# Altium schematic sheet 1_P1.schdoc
size 429 x 307 mm; Symbol: Drawing-Symbol_A4; Device: Drawing-Symbol_A4; @Project Name: PBT_PCB; @Page Count: 1; @Update Date: 2026-06-25; @Create Date: 2026-04-29; @Schematic Name: Schematic3; @Page No: 1; @Page Name: P1; Company: EasyEDA.com; Version: V1.0; Page Size: A4; @Create Time: 15:17:22; @Update Time: 19:14:14; Width: 1655; Height: 1170; Region Start: 1; X Region Count: 6; Y Region Count: 4; Blade Width: 10; Title Block Position: 3; @Board Name: NRF board
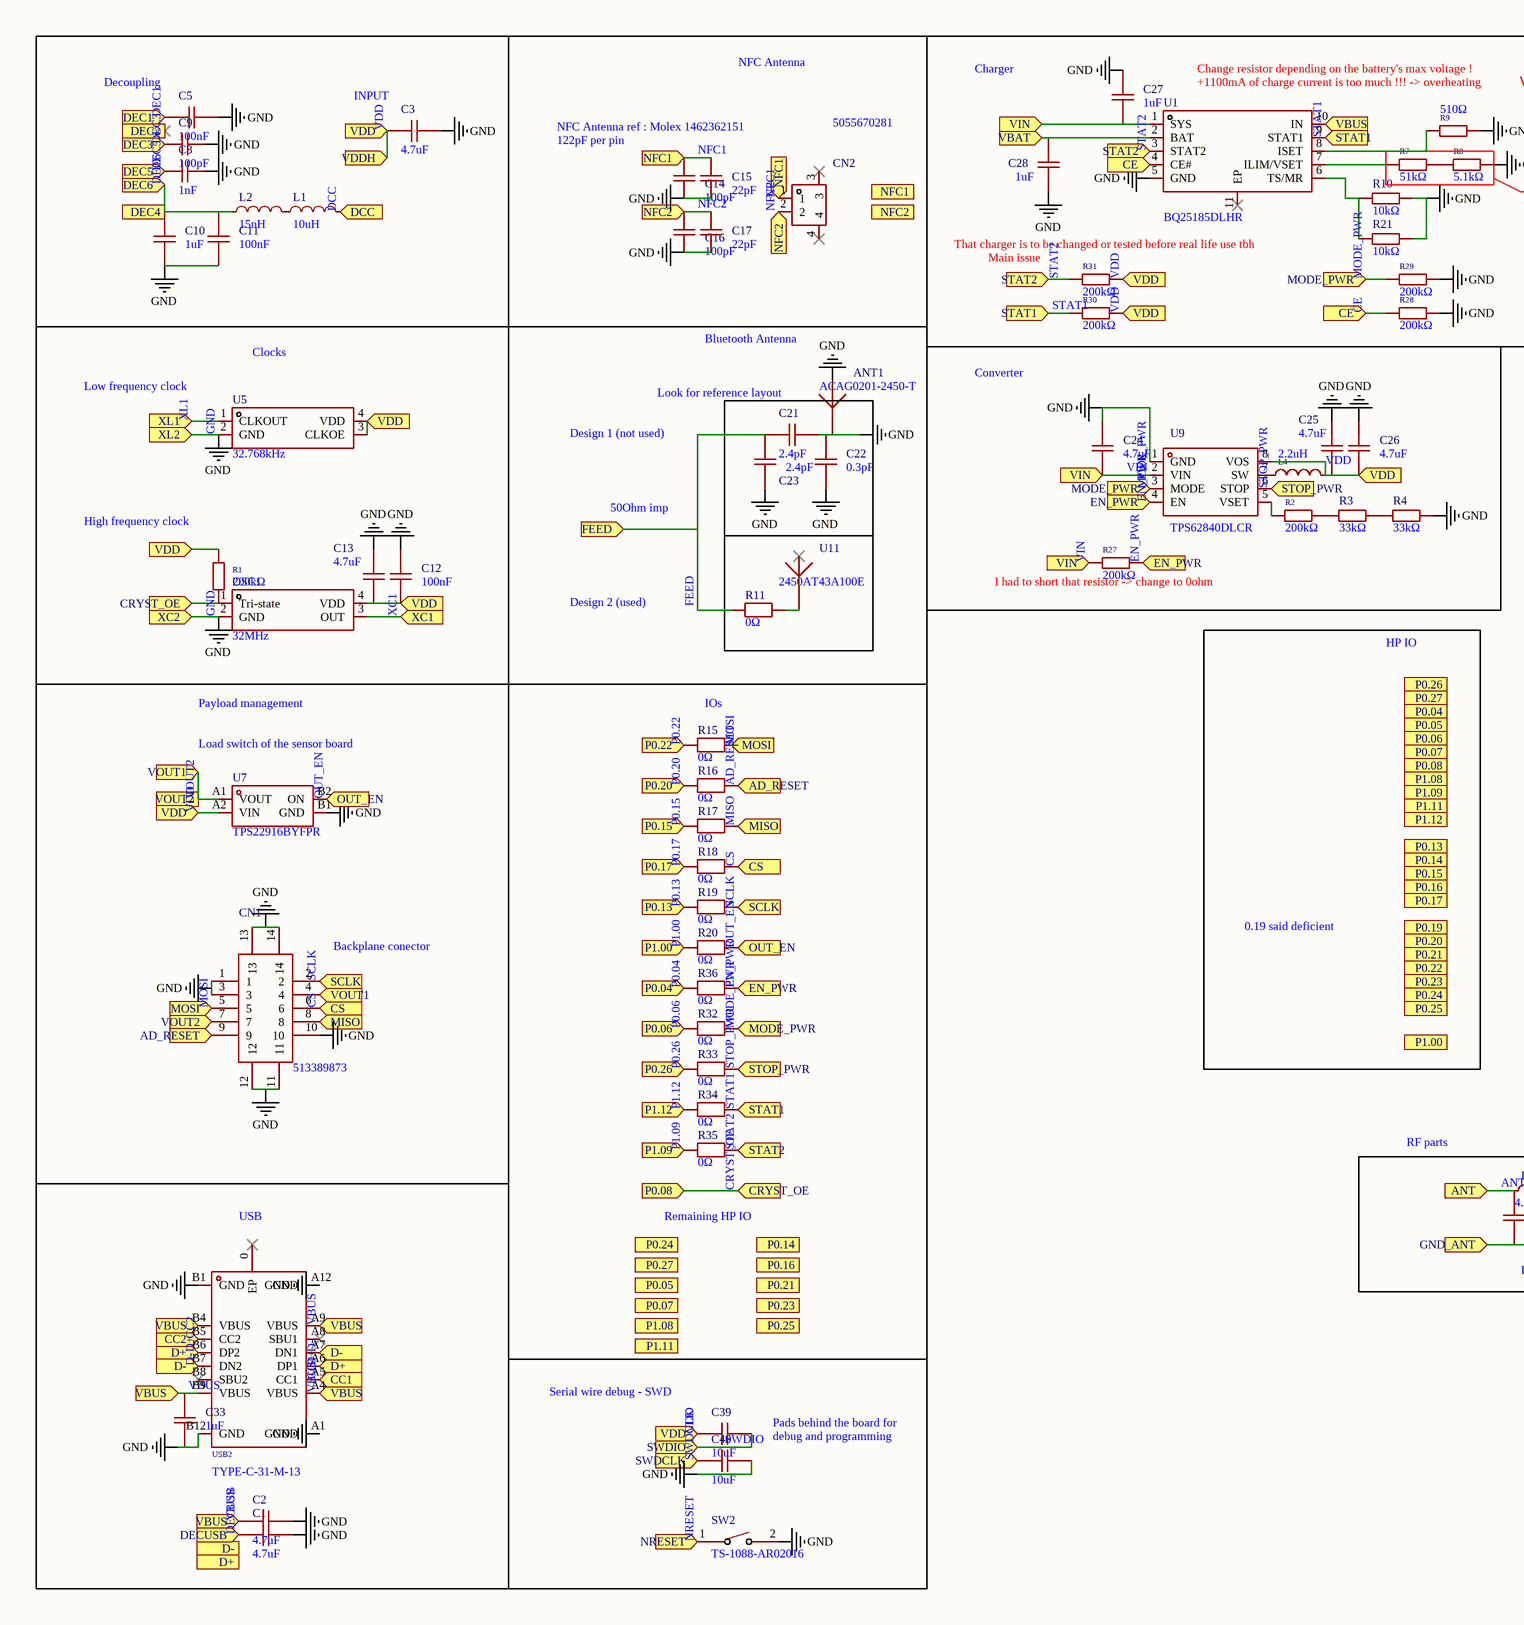
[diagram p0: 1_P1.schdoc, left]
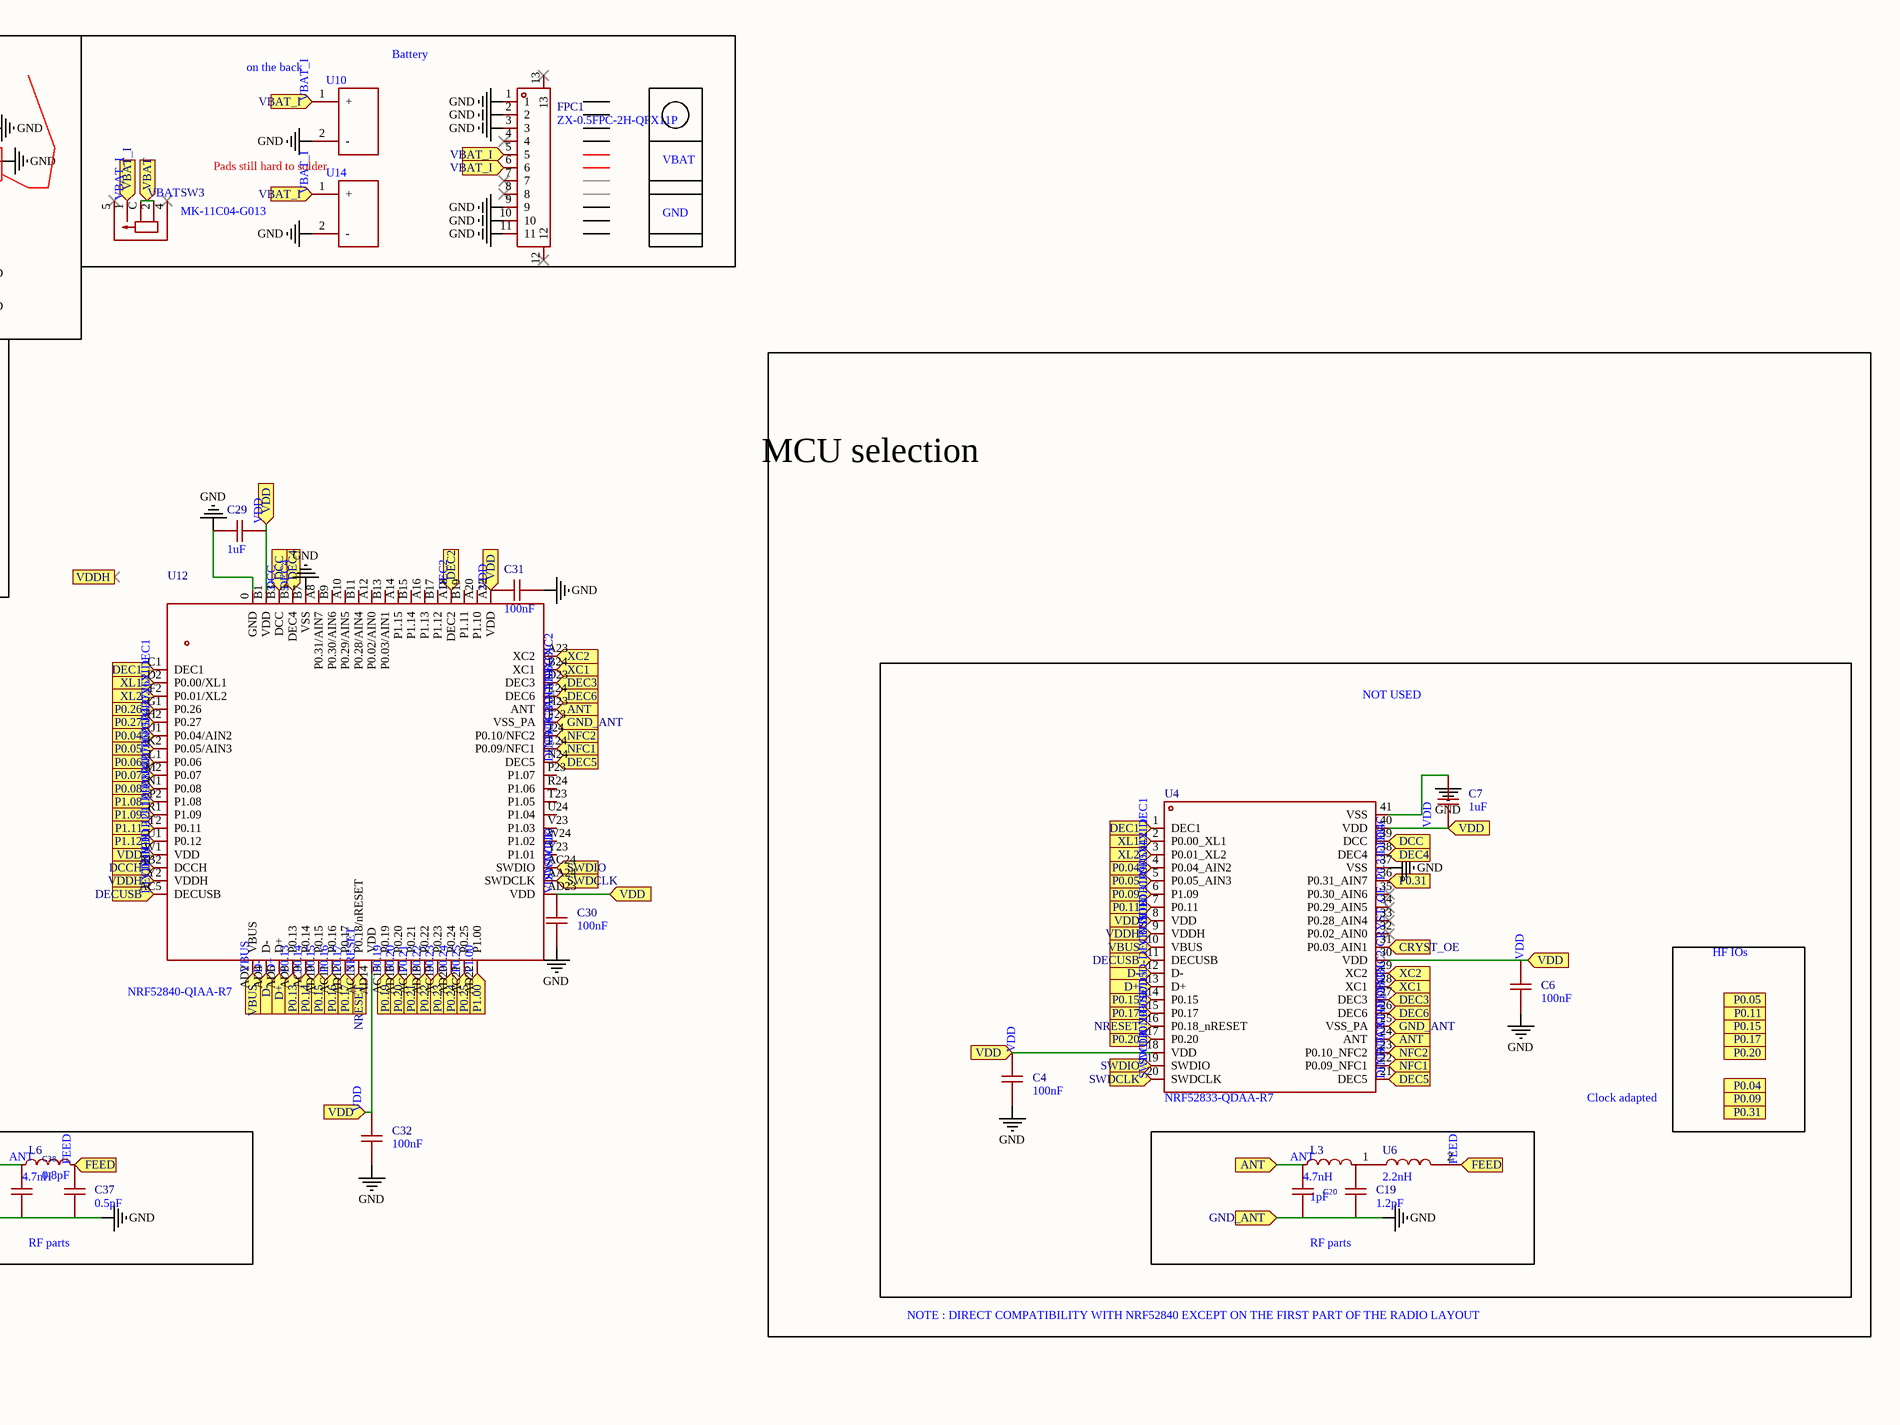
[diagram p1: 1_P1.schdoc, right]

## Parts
ANT1  ACAG0201-2450-T  [ANT-SMD_L2.0-W1.3_ACAG0201-2450-T]
C1  4.7uF  [C0402]
C2  4.7uF  [C0402]
C3  4.7uF  [C0402]
C4  100nF  [C0402]
C5  100nF  [C0402]
C6  100nF  [C0402]
C7  1uF  [C0402]
C8  1nF  [C0402]
C9  100pF  [C0402]
C10  1uF  [C0402]
C11  100nF  [C0402]
C12  100nF  [C0402]
C13  4.7uF  [C0402]
C14  100pF  [C0402]
C15  22pF  [C0402]
C16  100pF  [C0402]
C17  22pF  [C0402]
C19  1.2pF  [C0402]
C20  1pF  [C0402]
C21  2.4pF  [C0402]
C22  0.3pF  [C0603]
C23  2.4pF  [C0402]
C24  4.7uF  [C0402]
C25  4.7uF  [C0402]
C26  4.7uF  [C0402]
C27  1uF  [C0402]
C28  1uF  [C0402]
C29  1uF  [C0402]
C30  100nF  [C0402]
C31  100nF  [C0402]
C32  100nF  [C0402]
C33  1uF  [C0402]
C37  0.5pF  [C0402]
C38  0.8pF  [C0402]
C39  10uF  [C0805]
C40  10uF  [C0805]
CN1  513389873  [CONN-SMD_513389873]
CN2  5055670281  [CONN-SMD_2P-P1.25_MOLEX_5055670281]
FPC1  ZX-0.5FPC-2H-QFX11P  [FPC-SMD_11P-P0.50_ZX-0.5FPC-2H-QFX11P]
L1  10uH  [L0603]
L2  15nH  [IND-SMD_L1.2-W0.6]
L3  4.7nH  [L0402]
L4  2.2uH  [IND-SMD_L2.0-W1.6_MHCHL201610A-1R0M-Q8A]
L6  4.7nH  [L0402]
OSC1  32MHz  [OSC-SMD_4P-L3.2-W2.5-BL]
R1  200kΩ  [R0402]
R2  200kΩ  [R0402]
R3  33kΩ  [R0402]
R4  33kΩ  [R0402]
R7  51kΩ  [R0402]
R8  5.1kΩ  [R0402]
R9  510Ω  [R0402]
R10  10kΩ  [R0402]
R11  0Ω  [R0402]
R15  0Ω  [R0402]
R16  0Ω  [R0402]
R17  0Ω  [R0402]
R18  0Ω  [R0402]
R19  0Ω  [R0402]
R20  0Ω  [R0402]
R21  10kΩ  [R0402]
R27  200kΩ  [R0402]
R28  200kΩ  [R0402]
R29  200kΩ  [R0402]
R30  200kΩ  [R0402]
R31  200kΩ  [R0402]
R32  0Ω  [R0402]
R33  0Ω  [R0402]
R34  0Ω  [R0402]
R35  0Ω  [R0402]
R36  0Ω  [R0402]
SW2  TS-1088-AR02016  [SW-SMD_L3.9-W3.0-P4.45]
SW3  MK-11C04-G013  [SW-SMD_MK-11C04-G013]
U1  BQ25185DLHR  [WSON-10_L2.2-W2.0-P0.40-BL-EP_TI_DLH0010A]
U4  NRF52833-QDAA-R7  [QFN-40_L5.0-W5.0-P0.40-TL-EP3.6]
U5  32.768kHz  [OSC-SMD_4P-L3.2-W1.5-BL]
U6  2.2nH  [L0402]
U7  TPS22916BYFPR  [DSBGA-4_L0.8-W0.8-R2-C2-P0.40-BL]
U9  TPS62840DLCR  [VSON-8_L2.0-W1.5-P0.50-BL]
U10  (no value)  [CSSMR950SH_CONN]
U11  2450AT43A100E  [ANT-SMD_L7.0-W2.0-R]
U12  NRF52840-QIAA-R7  [AQFN-73_L7.0-W7.0-P0.50-BL-EP4.8]
U14  (no value)  [CSSMR950SH_CONN]
USB2  TYPE-C-31-M-13  [USB-C-SMD_TYPE-C-31-M-13]

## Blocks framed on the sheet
NFC Antenna: C14-C17 CN2
RF parts: C19 C20 L3 U6
USB: C1 C2 C33 USB2
Serial wire debug - SWD: C39 C40 SW2

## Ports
AD_RESET (in), ANT (in), CC1 (in), CC2 (in), CE (in), CRYST_OE (in), CS (in), D+ (in), D- (in), DCC (in), DCCH (in), DEC1 (in), DEC2 (in), DEC3 (in), DEC4 (in), DEC5 (in), DEC6 (in), DECUSB (in), EN_PWR (in), FEED (in), GND_ANT (in), MISO (in), MODE_PWR (in), MOSI (in), NFC1 (in), NFC2 (in), NRESET (in), OUT_EN (in), P0.04 (in), P0.05 (in), P0.06 (in), P0.07 (in), P0.08 (in), P0.09 (in), P0.11 (in), P0.13 (in), P0.14 (in), P0.15 (in), P0.16 (in), P0.17 (in), P0.19 (in), P0.20 (in), P0.21 (in), P0.22 (in), P0.23 (in), P0.24 (in), P0.25 (in), P0.26 (in), P0.27 (in), P0.31 (in), P1.00 (in), P1.08 (in), P1.09 (in), P1.11 (in), P1.12 (in), SCLK (in), STAT1 (in), STAT2 (in), STOP_PWR (in), SWDCLK (in), SWDIO (in), VBAT (in), VBAT_I (in), VBUS (in), VDD (in), VDDH (in), VIN (in), VOUT1 (in), VOUT2 (in), XC1 (in), XC2 (in), XL1 (in), XL2 (in)

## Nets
GND: ANT1.1 ANT1.2 C1.2 C2.2 C3.2 C4.2 C5.2 C6.2 C7.1 C8.2 C9.2 C10.1 C11.2 C12.1 C13.1 C14.2 C15.2 C16.2 C17.2 C19.2 C20.1 C21.2 C22.1 C22.2 C23.2 C24.1 C25.1 C26.1 C27.2 C28.2 C29.2 C30.2 C31.2 C32.2 C33.2 C37.2 C38.1 C40.1 CN1.1 CN1.3 CN1.10 CN1.11 CN1.12 CN1.13 CN1.14 FPC1.1 FPC1.2 FPC1.3 FPC1.9 FPC1.10 FPC1.11 OSC1.2(GND) R4.2 R8.2 R9.2 R10.2 R21.2 R28.2 R29.1 SW2.2 U1.5(GND) U4.3(P0.01_XL2) U4.25(VSS_PA) U4.29(XC2) U4.37(VSS) U4.41(VSS) U5.2(GND) U7.B1(GND) U9.1(GND) U10.2(-) U12.0(GND) U12.A23(XC2) U12.B7(VSS) U12.F2(P0.01/XL2) U12.F23(VSS_PA) U14.2(-) USB2.A1(GND) USB2.A12(GND) USB2.B1(GND) USB2.B12(GND) ; port XC2, port XL2, port GND_ANT  [also labelled GND_ANT, XC2, XL2]
AD_RESET: CN1.9 R16.2 ; port AD_RESET
ANT: C20.2 C38.2 L3.1 L6.1 U4.24(ANT) U12.H23(ANT) ; port ANT
CC1: USB2.A5(CC1) ; port CC1
CC2: USB2.B5(CC2) ; port CC2
CE: R28.1 U1.4(CE#) ; port CE
CRYST_OE: OSC1.1(Tri-state) R1.2 U4.31(P0.03_AIN1) U12.N1(P0.08) ; port CRYST_OE, port P0.08  [also labelled P0.08]
CS: CN1.6 R18.2 ; port CS
D+: U4.13(D+) U12.AD6(D+) USB2.A6(DP1) USB2.B6(DP2) ; port D+
D-: U4.12(D-) U12.AD4(D-) USB2.A7(DN1) USB2.B7(DN2) ; port D-
DCC: L1.2 U4.39(DCC) U12.B3(DCC) ; port DCC
DCCH: U12.AB2(DCCH) ; port DCCH
DEC1: C5.1 U4.1(DEC1) U12.C1(DEC1) ; port DEC1
DEC2: U12.A18(DEC2) ; port DEC2
DEC3: C9.1 U4.27(DEC3) U12.D23(DEC3) ; port DEC3
DEC4: C10.2 C11.1 L2.1 U4.26(DEC6) U4.38(DEC4) U12.B5(DEC4) U12.E24(DEC6) ; port DEC4, port DEC6  [also labelled DEC6]
DEC5: C8.1 U4.21(DEC5) U12.N24(DEC5) ; port DEC5
DECUSB: C1.1 U4.11(DECUSB) U12.AC5(DECUSB) ; port DECUSB
EN_PWR: R27.1 R36.2 U9.4(EN) ; port EN_PWR
FEED: C21.1 C23.1 C37.1 L6.2 R11.1 U6.2 ; port FEED
MISO: CN1.8 R17.2 ; port MISO
MODE_PWR: R29.2 R32.2 U9.3(MODE) ; port MODE_PWR
MOSI: CN1.5 R15.2 ; port MOSI
NFC1: C14.1 C15.1 CN2.1 U4.22(P0.09_NFC1) U12.L24(P0.09/NFC1) ; port NFC1
NFC2: C16.1 C17.1 CN2.2 U4.23(P0.10_NFC2) U12.J24(P0.10/NFC2) ; port NFC2
NRESET: SW2.1 U4.16(P0.18_nRESET) U12.AC13(P0.18/nRESET) ; port NRESET
OUT_EN: R20.2 U7.B2(ON) ; port OUT_EN
P0.04: R36.1 U4.4(P0.04_AIN2) U12.J1(P0.04/AIN2) ; port P0.04
P0.05: U4.5(P0.05_AIN3) U12.K2(P0.05/AIN3) ; port P0.05
P0.06: R32.1 U12.L1(P0.06) ; port P0.06
P0.07: U12.M2(P0.07) ; port P0.07
P0.09: U4.6(P1.09) ; port P0.09
P0.11: U4.7(P0.11) ; port P0.11
P0.13: R19.1 U12.AD8(P0.13) ; port P0.13
P0.14: U12.AC9(P0.14) ; port P0.14
P0.15: R17.1 U4.14(P0.15) U12.AD10(P0.15) ; port P0.15
P0.16: U12.AC11(P0.16) ; port P0.16
P0.17: R18.1 U4.15(P0.17) U12.AD12(P0.17) ; port P0.17
P0.19: U12.AC15(P0.19) ; port P0.19
P0.20: R16.1 U4.17(P0.20) U12.AD16(P0.20) ; port P0.20
P0.21: U12.AC17(P0.21) ; port P0.21
P0.22: R15.1 U12.AD18(P0.22) ; port P0.22
P0.23: U12.AC19(P0.23) ; port P0.23
P0.24: U12.AD20(P0.24) ; port P0.24
P0.25: U12.AC21(P0.25) ; port P0.25
P0.26: R33.1 U12.G1(P0.26) ; port P0.26
P0.27: U12.H2(P0.27) ; port P0.27
P0.31: U4.36(P0.31_AIN7) ; port P0.31
P1.00: R20.1 U12.AD22(P1.00) ; port P1.00
P1.08: U12.P2(P1.08) ; port P1.08
P1.09: R35.1 U12.R1(P1.09) ; port P1.09
P1.11: U12.T2(P0.11) ; port P1.11
P1.12: R34.1 U12.U1(P0.12) ; port P1.12
SCLK: CN1.2 R19.2 ; port SCLK
STAT1: R30.2 R34.2 U1.9(STAT1) ; port STAT1
STAT2: R31.2 R35.2 U1.3(STAT2) ; port STAT2
STOP_PWR: R33.2 U9.6(STOP) ; port STOP_PWR
SWDCLK: C40.2 U4.20(SWDCLK) U12.AA24(SWDCLK) ; port SWDCLK
SWDIO: C39.2 U4.19(SWDIO) U12.AC24(SWDIO) ; port SWDIO
VBAT: C28.1 SW3.2 SW3.C U1.2(BAT) ; port VBAT
VBAT_I: FPC1.5 FPC1.6 SW3.1 U10.1(+) U14.1(+) ; port VBAT_I
VBUS: C2.1 C33.1 U1.10(IN) U4.10(VBUS) U12.AD2(VBUS) USB2.A4(VBUS) USB2.A9(VBUS) USB2.B4(VBUS) USB2.B9(VBUS) ; port VBUS
VDD: C3.1 C4.1 C6.1 C7.2 C12.2 C13.2 C25.2 C26.2 C29.1 C30.1 C31.1 C32.1 C39.1 L4.2 OSC1.4(VDD) R1.1 R30.1 R31.1 U4.8(VDD) U4.9(VDDH) U4.18(VDD) U4.30(VDD) U4.40(VDD) U5.3(CLKOE) U5.4(VDD) U7.A2(VIN) U9.8(VOS) U12.A22(VDD) U12.AD14(VDD) U12.AD23(VDD) U12.B1(VDD) U12.W1(VDD) U12.Y2(VDDH) ; port VDD, port VDDH  [also labelled VDDH]
VIN: C24.2 C27.1 R27.2 U1.1(SYS) U9.2(VIN) ; port VIN
VOUT2: CN1.4 CN1.7 U7.A1(VOUT) ; port VOUT1, port VOUT2
XC1: OSC1.3(OUT) U4.28(XC1) U12.B24(XC1) ; port XC1
XL1: U4.2(P0.00_XL1) U5.1(CLKOUT) U12.D2(P0.00/XL1) ; port XL1
NetC19_1: C19.1 L3.2 U6.1
NetL1_1: L1.1 L2.2
NetL4_1: L4.1 U9.7(SW)
NetR2_1: R2.1 U9.5(VSET)
NetR2_2: R2.2 R3.1
NetR3_2: R3.2 R4.1
NetR7_1: R7.1 U1.7(ILIM/VSET)
NetR7_2: R7.2 R8.1
NetR9_1: R9.1 U1.8(ISET)
NetR10_1: R10.1 R21.1 U1.6(TS/MR)
NetR11_2: R11.2 U11.1(ANT)

Not connected (* = marked no-connect by the designer): CN2 3* 4*; FPC1 4* 7* 8* 12* 13*; SW3 4* 5*; U1 11(EP)*; U4 32(P0.02_AIN0)* 33(P0.28_AIN4)* 34(P0.29_AIN5)* 35(P0.30_AIN6)*; U11 2*; U12 A8(P0.31/AIN7) A10(P0.29/AIN5) A12(P0.02/AIN0) A14(P1.15) A16(P1.13) A20(P1.10) B9(P0.30/AIN6) B11(P0.28/AIN4) B13(P0.03/AIN1) B15(P1.14) B17(P1.12) B19(P1.11) P23(P1.07) R24(P1.06) T23(P1.05) U24(P1.04) V23(P1.03) W24(P1.02) Y23(P1.01); USB2 0(EP)* A8(SBU1)* B8(SBU2)*

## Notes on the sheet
- (near C5) Decoupling
- (near C3) INPUT
- Charger
- Change resistor depending on the battery's max voltage !
- +1100mA of charge current is too much !!! -> overheating
- (near U10) on the back
- Battery
- NFC Antenna ref : Molex 1462362151
  122pF per pin
- Pads still hard to solder
- VBAT
- GND
- That charger is to be changed or tested before real life use tbh
- Main issue
- Clocks
- (near ANT1) Bluetooth Antenna
- (near U5) Low frequency clock
- Design 1 (not used)
- Look for reference layout
- Converter
- MCU selection
- (near R1) High frequency clock
- 50Ohm imp
- Design 2 (used)
- (near R27) I had to short that resistor -> change to 0ohm
- Payload management
- (near R15) IOs
- HP IO
- NOT USED
- (near U7) Load switch of the sensor board
- (near CN1) Backplane conector
- 0.19 said deficient
- HF IOs
- RF parts
- Clock adapted
- Remaining HP IO
- NOTE : DIRECT COMPATIBILITY WITH NRF52840 EXCEPT ON THE FIRST PART OF THE RADIO LAYOUT
- (near SW2) Pads behind the board for
  debug and programming

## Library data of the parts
ANT1 = ACAG0201-2450-T: Manufacturer: ABRACON; Add into BOM: yes; Convert to PCB: no; Antenna Type: Ceramic Antenna; Frequency(Center/Band): 2.4GHz; Bandwidth: 65MHz; Peak Gain: 2.7dBi; Impedance: 50Ω; VSWR: 2
C1-C3 C13 C24-C26 = CL05A475MP5NRNC: Manufacturer: SAMSUNG(三星); Add into BOM: yes; Tolerance: ±20%; Voltage Rating: 10V; Temperature Coefficient: X5R
C4 C6 = CL05B104KO5NNNC: Manufacturer: SAMSUNG(三星); Add into BOM: no; Tolerance: ±10%; Voltage Rating: 16V; Temperature Coefficient: X7R
C5 C11 C12 C30-C32 = CL05B104KO5NNNC: Manufacturer: SAMSUNG(三星); Add into BOM: yes; Tolerance: ±10%; Voltage Rating: 16V; Temperature Coefficient: X7R
C7 = CL05A105KA5NQNC: Manufacturer: SAMSUNG(三星); Add into BOM: no; Tolerance: ±10%; Voltage Rating: 25V; Temperature Coefficient: X5R
C8 = 0402B102K500NT: Manufacturer: FH(风华); Add into BOM: yes; Tolerance: ±10%; Voltage Rating: 50V; Temperature Coefficient: X7R
C9 C14 C16 = 0402CG101J500NT: Manufacturer: FH(风华); Add into BOM: yes; Tolerance: ±5%
C10 C27-C29 C33 = CL05A105KA5NQNC: Manufacturer: SAMSUNG(三星); Add into BOM: yes; Tolerance: ±10%; Voltage Rating: 25V; Temperature Coefficient: X5R
C15 C17 = 0402CG220J500NT: Manufacturer: FH(风华); Add into BOM: yes; Tolerance: ±5%; Voltage Rating: 50V; Temperature Coefficient: C0G
C19 = RF15N1R2A500CT: Manufacturer: Walsin(华新科); Add into BOM: no
C20 = RF15N1R0A500CT: Manufacturer: Walsin(华新科); Add into BOM: no; Voltage Rating: 50V; Temperature Coefficient: NP0
C21 = RF15N2R4A500CT: Manufacturer: Walsin(华新科); Add into BOM: yes; Convert to PCB: no
C22 = CQ0603ARNPO0BNR30: Manufacturer: YAGEO(国巨); Add into BOM: yes; Convert to PCB: no; Voltage Rating: 100V; Temperature Coefficient: NP0
C23 = RF15N2R4A500CT: Manufacturer: Walsin(华新科); Add into BOM: no
C37 = RF15N0R5A500CT: Manufacturer: Walsin(华新科); Add into BOM: yes
C38 = RF15N0R8B500CT_C396870: Manufacturer: Walsin(华新科); Symbol: RF15N0R8B500LT; Add into BOM: yes; Voltage Rating: 50V; Temperature Coefficient: NP0
C39 C40 = CL21A106KAYNNNE_C15850: Manufacturer: SAMSUNG(三星); Add into BOM: no; Convert to PCB: yes; Tolerance: ±10%; Voltage Rating: 25V; Temperature Coefficient: X5R
CN1 = 513389873: Manufacturer: MOLEX; Add into BOM: yes; Pitch: 0.4mm; Current Rating: 300mA; Voltage Rating: 50V; System Fit Height: 2mm；1.5mm
CN2 = 5055670281: Manufacturer: MOLEX; Add into BOM: no; Pins Structure: 1x2P; Pitch: 1.25mm; Number of PINs Per Row: 2; Current Rating: 1.5A; Voltage Rating: 50V; Flame Retardant Rating: UL94V-0
FPC1 = ZX-0.5FPC-2H-QFX11P: Manufacturer: Megastar(兆星); Add into BOM: no; Locking Feature: Hinged Lid; Number of Contacts: 11P; Pitch: 0.5mm; FFC, FCB Thickness: 0.3mm; Rated Voltage (Max): 50V
L1 = LQM18DN100M70L: Manufacturer: muRata(村田); Add into BOM: yes; Tolerance: ±20%; Frequency - Self Resonant: 32MHz
L2 = AISC-0402-15NJ-T: Manufacturer: ABRACON; Add into BOM: yes; Tolerance: ±5%; Current Rating: 560mA; Q @ Frequency: 26@250MHz; Frequency - Self Resonant: 3.28GHz
L3 = VHF100505HQ4N7ST: Manufacturer: FH(风华); Add into BOM: no; Current Rating: 300mA; DC Resistance(DCR): 200mΩ
L4 = WIP201610P-2R2ML: Manufacturer: INPAQ(佳邦); Add into BOM: yes; Tolerance: ±20%
L6 = VHF100505HQ4N7ST: Manufacturer: FH(风华); Add into BOM: yes; Current Rating: 300mA; DC Resistance(DCR): 200mΩ
OSC1 = OT2EL89CJI-111YLC-32M: Manufacturer: YXC(扬兴晶振); Add into BOM: yes; Normal temperature Frequency Tolerance: ±10ppm; Output Type: CMOS; Voltage - Supply: 1.8V~3.3V; Frequency Stability: ±20ppm
R1 R2 R27-R31 = 0402WGF2003TCE: Manufacturer: UNI-ROYAL(厚声); Add into BOM: yes; Tolerance: ±1%; Power(Watts): 62.5mW; Voltage-Supply(Max): 50V; Temperature Coefficient: ±100ppm/℃
R3 R4 = 0402WGF3302TCE: Manufacturer: UNI-ROYAL(厚声); Add into BOM: yes; Tolerance: ±1%; Temperature Coefficient: ±100ppm/℃
R7 = 0402WGF5102TCE: Manufacturer: UNI-ROYAL(厚声); Add into BOM: yes; Tolerance: ±1%; Temperature Coefficient: ±100ppm/℃
R8 = 0402WGF5101TCE: Manufacturer: UNI-ROYAL(厚声); Add into BOM: yes; Tolerance: ±1%; Power(Watts): 62.5mW; Voltage-Supply(Max): 50V; Temperature Coefficient: ±100ppm/℃
R9 = 0402WGF5100TCE: Manufacturer: UNI-ROYAL(厚声); Add into BOM: yes; Tolerance: ±1%; Power(Watts): 62.5mW; Voltage-Supply(Max): 50V; Temperature Coefficient: ±100ppm/℃
R10 = 0402WGF1002TCE: Manufacturer: UNI-ROYAL(厚声); Add into BOM: yes; Tolerance: ±1%; Power(Watts): 62.5mW; Voltage-Supply(Max): 50V; Temperature Coefficient: ±100ppm/℃
R11 R15-R20 R32-R36 = CRCW04020000Z0EDHP: Manufacturer: VISHAY(威世); Add into BOM: yes; Power(Watts): 200mW; Voltage-Supply(Max): 50V
R21 = 0402WGF1002TCE: Manufacturer: UNI-ROYAL(厚声); Add into BOM: no; Convert to PCB: yes; Tolerance: ±1%; Power(Watts): 62.5mW; Voltage-Supply(Max): 50V; Temperature Coefficient: ±100ppm/℃
SW2 = TS-1088-AR02016: Manufacturer: XUNPU(讯普); Add into BOM: yes; Circuit: SPST; Actuator Style: Round Button; Operating Force: 1.6N; Switch Height: 2mm; with Bracket: Without Bracket; Contact Current: 50mA; Voltage Rating: 12V; Actuator/Cap Color: Black; Life: 100,000 Cycles
SW3 = MK-11C04-G013: Manufacturer: G-Switch(品赞); Add into BOM: yes; Circuit: SPDT; Actuator Style: Rectangular Columnar; Switch Height: 3.8mm; Actuator Color: Black; Current Rating: 1A; Voltage Rating: 6V; Life: 10,000 Cycles
U1 = BQ25185DLHR: Manufacturer: TI(德州仪器); Add into BOM: yes; The Chip Type: Charging IC; Voltage - Supply: 3V~18V; Charge Current - Max: 1A; Charging Saturation Voltage: 4.4V; End-Off Voltage: 2.2V; Type of Battery: Lithium Battery；LiFePO4 Battery; Number of Cells: 1; Battery Temperature Detection: Support; Supply Current (Iq): 4uA
U4 = NRF52833-QDAA-R7: Manufacturer: NORDIC; Add into BOM: no; Frequency Range: 2.4GHz~2.4835GHz; Interface: ADC；PWM；I2S；UART；USB；SPI; Voltage - Supply: 1.7V~5.5V; Output Power: 8dBm; Data Rate: 2Mbps; Typical Application Frequency: 2.4GHz
U5 = OV-7604-C7-32.768kHz-20PPM-TA-QC: Manufacturer: Micro Crystal(瑞士微晶); Add into BOM: yes; Normal temperature Frequency Tolerance: ±20ppm
U6 = VHF100505HQ2N2BT: Manufacturer: FH(风华); Add into BOM: no
U7 = TPS22916BYFPR: Manufacturer: TI(德州仪器); Add into BOM: yes; Number of Channels: 1; Control Input Logic: Active High; Voltage - Supply: 1V~5.5V; RDS(on): 60mΩ
U9 = TPS62840DLCR: Manufacturer: TI(德州仪器); Add into BOM: yes; Function: Buck; Voltage - Supply: 1.8V~6.5V; Output Voltage: 1.8V~3.3V; Output Current: 750mA; Frequency - Switching: 1.8MHz; Number of Outputs: 1; Quiescent Current: 60nA; Switch tube (built-in/external): Built-in; Output Type: Adjustable
U10 U14 = CSSMR950SH_CONN: Add into BOM: yes
U11 = 2450AT43A100E: Manufacturer: JOHANSON(约翰逊); Add into BOM: yes; Antenna Type: 2.4G Antenna; Frequency(Center/Band): 2.4GHz; Peak Gain: 2dBi; Impedance: 50Ω; Power: 2W; VSWR: 1.5
U12 = NRF52840-QIAA-R7: Manufacturer: NORDIC; Add into BOM: yes; Frequency Range: 2.4GHz~2.4835GHz; Interface: I2S；SPI；PDM；USB；PWM；UART; Voltage - Supply: 1.7V~5.5V; Output Power: 8dBm; Data Rate: 2Mbps; Current Of Transmitting: 4.82mA; Sensitivity: -95dBm; Receive Current: 6.26mA; Typical Application Frequency: 2.4GHz
USB2 = TYPE-C-31-M-13: Manufacturer: 韩国韩荣; Add into BOM: yes; Connector Type: Type-C; Gender: Female; Number of Contacts: 12P; Number of Ports: 1; Current Rating-Power: 3A; Voltage Rating: 100V; Connect-Disconnect Life: 10,000 cycles; Detection color: Black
